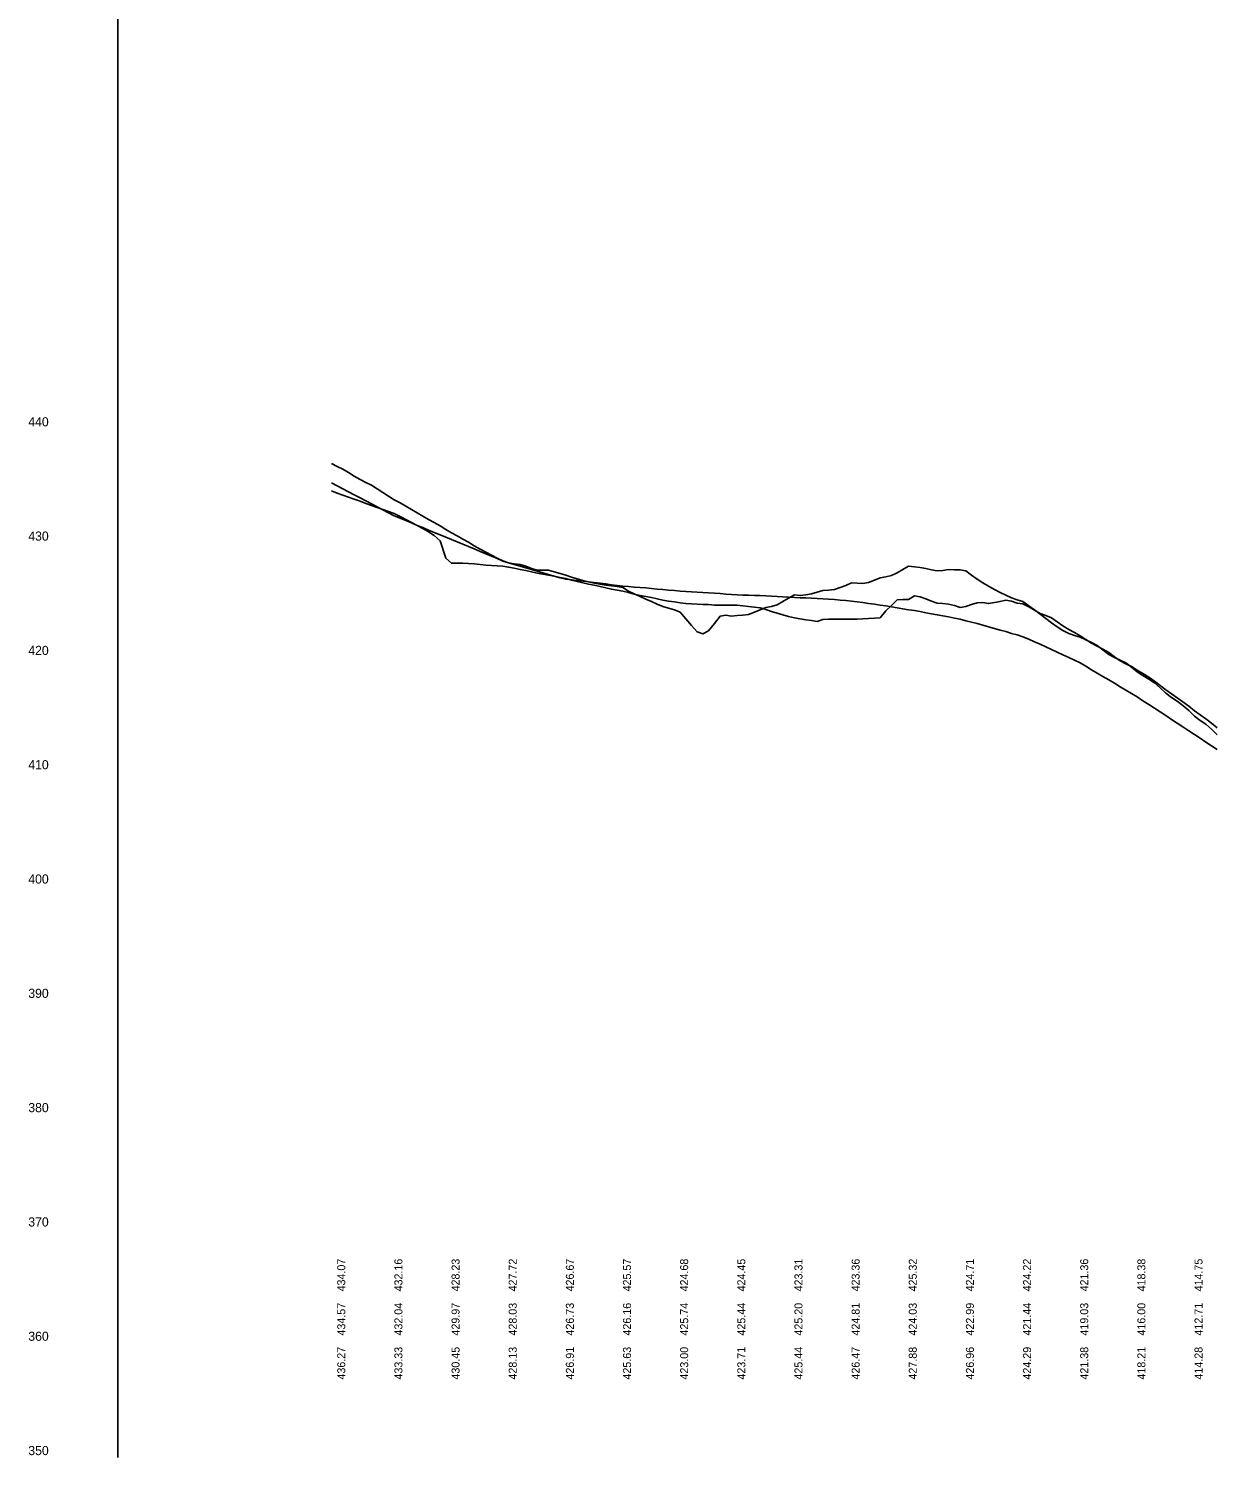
# Model space of a CAD drawing. Extents: x 2116146 to 2121546, y 979095 to 984095.
# Drawn here: x 2117491 to 2118529, y 981595 to 982845 of the extents above; entities that cross this region are included whole.
import ezdxf

# ---------------------------------------------------------------- set-up
doc = ezdxf.new("R2010")
doc.units = 0
for name, color, linetype in [('RD_DDB_ElevTX', 7, 'Continuous'), ('RD_DDB_Profile_EX', 7, 'Continuous'), ('RD_DDB_StripGrade', 7, 'Continuous'), ('RD_GPK_Profile_Cell', 7, 'Continuous'), ('RD_Sketch2', 7, 'Continuous')]:
    doc.layers.add(name, color=color, linetype=linetype)

msp = doc.modelspace()

# ---------------------------------------------------------------- linework, layer by layer
at = {"layer": 'RD_DDB_Profile_EX'}
for points in [[(2117756, 982448.1), (2117761, 982445.5), (2117766, 982442.8), (2117771, 982440.2), (2117776, 982437.6), (2117781, 982434.9), (2117786, 982432.3), (2117791, 982429.7), (2117796, 982427), (2117801, 982424.4), (2117806, 982421.7), (2117811, 982419.2), (2117816, 982417.2), (2117821, 982415.1), (2117826, 982413), (2117831, 982410.9), (2117836, 982408.9), (2117841, 982406.8), (2117846, 982404.7), (2117851, 982402.6), (2117856, 982400.6), (2117861, 982398.5), (2117866, 982396.4), (2117871, 982394.4), (2117876, 982392.3), (2117881, 982390.2), (2117886, 982388.1), (2117891, 982386.1), (2117896, 982384), (2117901, 982381.9), (2117906, 982379.7), (2117911, 982378), (2117916, 982376.6), (2117921, 982375.2), (2117926, 982373.8), (2117931, 982372.4), (2117936, 982370.9), (2117941, 982369.4), (2117946, 982367.9), (2117951, 982366.4), (2117956, 982364.9), (2117961, 982363.7), (2117966, 982363.1), (2117971, 982362.6), (2117976, 982362.1), (2117981, 982361.5), (2117986, 982360.9), (2117991, 982360.2), (2117996, 982359.6), (2118001, 982358.9), (2118006, 982358.2), (2118011, 982357.6), (2118016, 982357.3), (2118021, 982356.9), (2118026, 982356.5), (2118031, 982356.1), (2118036, 982355.7), (2118041, 982355.2), (2118046, 982354.8), (2118051, 982354.3), (2118056, 982353.8), (2118061, 982353.3), (2118066, 982353), (2118071, 982352.8), (2118076, 982352.5), (2118081, 982352.2), (2118086, 982351.8), (2118091, 982351.5), (2118096, 982351.2), (2118101, 982350.8), (2118106, 982350.4), (2118111, 982350.1), (2118116, 982349.9), (2118121, 982349.8), (2118126, 982349.6), (2118131, 982349.4), (2118136, 982349.2), (2118141, 982349), (2118146, 982348.7), (2118151, 982348.4), (2118156, 982348.2), (2118161, 982347.9), (2118166, 982347.6), (2118171, 982347.4), (2118176, 982347.1), (2118181, 982346.8), (2118186, 982346.5), (2118191, 982346.2), (2118196, 982345.9), (2118201, 982345.5), (2118206, 982345.1), (2118211, 982344.7), (2118216, 982344), (2118221, 982343.3), (2118226, 982342.6), (2118231, 982341.9), (2118236, 982341.1), (2118241, 982340.4), (2118246, 982339.6), (2118251, 982338.8), (2118256, 982338)], [(2118256, 982338), (2118261, 982337.1), (2118266, 982336.3), (2118271, 982335.4), (2118276, 982334.5), (2118281, 982333.6), (2118286, 982332.7), (2118291, 982331.7), (2118296, 982330.8), (2118301, 982329.8), (2118306, 982328.8), (2118311, 982327.5), (2118316, 982326.2), (2118321, 982324.9), (2118326, 982323.5), (2118331, 982322.1), (2118336, 982320.7), (2118341, 982319.3), (2118346, 982317.9), (2118351, 982316.4), (2118356, 982315), (2118361, 982313.5), (2118366, 982311.3), (2118371, 982309), (2118376, 982306.8), (2118381, 982304.5), (2118386, 982302.2), (2118391, 982299.9), (2118396, 982297.6), (2118401, 982295.3), (2118406, 982292.9), (2118411, 982290.6), (2118416, 982287.6), (2118421, 982284.6), (2118426, 982281.7), (2118431, 982278.7), (2118436, 982275.7), (2118441, 982272.7), (2118446, 982269.7), (2118451, 982266.7), (2118456, 982263.8), (2118461, 982260.8), (2118466, 982257.5), (2118471, 982254.2), (2118476, 982251), (2118481, 982247.7), (2118486, 982244.4), (2118491, 982241.1), (2118496, 982237.8), (2118501, 982234.5), (2118506, 982231.2), (2118511, 982227.9), (2118516, 982224.6), (2118521, 982221.3), (2118526, 982218.1), (2118531, 982214.8)]]:
    msp.add_lwpolyline(points, dxfattribs=at)
at = {"layer": 'RD_GPK_Profile_Cell'}
msp.add_line((2117569.1, 981595.5), (2117569.1, 984095.5), dxfattribs=at)
at = {"layer": 'RD_Sketch2'}
for points in [[(2117756, 982464.9), (2117761, 982462.5), (2117766, 982460), (2117771, 982457.1), (2117776, 982453.8), (2117781, 982450.9), (2117786, 982448.4), (2117791, 982445.9), (2117796, 982442.8), (2117801, 982439.5), (2117806, 982436.3), (2117811, 982433.3), (2117816, 982430.5), (2117821, 982427.7), (2117826, 982424.8), (2117831, 982421.8), (2117836, 982418.8), (2117841, 982416), (2117846, 982413.3), (2117851, 982410.4), (2117856, 982407.4), (2117861, 982404.4), (2117866, 982401.7), (2117871, 982398.9), (2117876, 982396.1), (2117881, 982393.1), (2117886, 982390.1), (2117891, 982387.4), (2117896, 982384.8), (2117901, 982382.3), (2117906, 982379.8), (2117911, 982378), (2117916, 982377.2), (2117921, 982376.5), (2117926, 982375.2), (2117931, 982373.2), (2117936, 982371.7), (2117941, 982371.6), (2117946, 982371.7), (2117951, 982370.3), (2117956, 982368.9), (2117961, 982367.3), (2117966, 982365.6), (2117971, 982364), (2117976, 982362.7), (2117981, 982361.4), (2117986, 982360.3), (2117991, 982359.3), (2117996, 982358.5), (2118001, 982357.9), (2118006, 982357.3), (2118011, 982356.4), (2118016, 982353.4), (2118021, 982350.9), (2118026, 982348.5), (2118031, 982346.4), (2118036, 982344.3), (2118041, 982341.9), (2118046, 982339.8), (2118051, 982338.3), (2118056, 982336.9), (2118061, 982335), (2118066, 982329.1), (2118071, 982323.3), (2118076, 982317.7), (2118081, 982315.9), (2118086, 982318.7), (2118091, 982324.9), (2118096, 982331.4), (2118101, 982332.2), (2118106, 982331.5), (2118111, 982331.9), (2118116, 982332.3), (2118121, 982332.8), (2118126, 982334.8), (2118131, 982336.9), (2118136, 982338.9), (2118141, 982339.9), (2118146, 982341.5), (2118151, 982344.3), (2118156, 982347.3), (2118161, 982350.1), (2118166, 982349.6), (2118171, 982350), (2118176, 982351.1), (2118181, 982352.4), (2118186, 982353.8), (2118191, 982354.2), (2118196, 982354.8), (2118201, 982356.4), (2118206, 982358.4), (2118211, 982360.5), (2118216, 982360.2), (2118221, 982360.1), (2118226, 982360.9), (2118231, 982362.8), (2118236, 982364.9), (2118241, 982365.8), (2118246, 982366.9), (2118251, 982369.3), (2118256, 982372.3)], [(2117756, 982441), (2117761, 982439.1), (2117766, 982437.3), (2117771, 982435.5), (2117776, 982433.7), (2117781, 982431.9), (2117786, 982430), (2117791, 982428.2), (2117796, 982426.5), (2117801, 982424.7), (2117806, 982422.9), (2117811, 982421.3), (2117816, 982418.7), (2117821, 982416.1), (2117826, 982413.5), (2117831, 982410.9), (2117836, 982408.1), (2117841, 982405.1), (2117846, 982402.1), (2117851, 982397.2), (2117856, 982382.1), (2117861, 982377.7), (2117866, 982377.7), (2117871, 982377.8), (2117876, 982377.6), (2117881, 982377.1), (2117886, 982376.6), (2117891, 982376.2), (2117896, 982375.7), (2117901, 982375.5), (2117906, 982375.1), (2117911, 982374.4), (2117916, 982373.3), (2117921, 982372.3), (2117926, 982371.3), (2117931, 982370.3), (2117936, 982369.2), (2117941, 982368.2), (2117946, 982367.2), (2117951, 982366.3), (2117956, 982365.3), (2117961, 982364.3), (2117966, 982363), (2117971, 982361.7), (2117976, 982360.5), (2117981, 982359.3), (2117986, 982358.5), (2117991, 982357.3), (2117996, 982356.2), (2118001, 982355), (2118006, 982354.3), (2118011, 982353.3), (2118016, 982352), (2118021, 982350.7), (2118026, 982349.4), (2118031, 982348.7), (2118036, 982347.7), (2118041, 982346.6), (2118046, 982345.5), (2118051, 982344.5), (2118056, 982344), (2118061, 982343.2), (2118066, 982342.6), (2118071, 982342.1), (2118076, 982341.9), (2118081, 982341.7), (2118086, 982341.6), (2118091, 982341.2), (2118096, 982341.1), (2118101, 982341.1), (2118106, 982341.1), (2118111, 982341.1), (2118116, 982340.4), (2118121, 982339.8), (2118126, 982339.2), (2118131, 982338.6), (2118136, 982337.3), (2118141, 982335.6), (2118146, 982334), (2118151, 982332.6), (2118156, 982331.2), (2118161, 982330), (2118166, 982329.1), (2118171, 982328.3), (2118176, 982327.6), (2118181, 982326.9), (2118186, 982328.4), (2118191, 982328.9), (2118196, 982328.8), (2118201, 982328.7), (2118206, 982328.8), (2118211, 982328.9), (2118216, 982328.9), (2118221, 982329.1), (2118226, 982329.3), (2118231, 982329.7), (2118236, 982330.1), (2118241, 982336.2), (2118246, 982340.9), (2118251, 982345.7), (2118256, 982346.1)], [(2118256, 982372.3), (2118261, 982375.1), (2118266, 982374.5), (2118271, 982374.1), (2118276, 982373), (2118281, 982371.9), (2118286, 982371), (2118291, 982371.5), (2118296, 982372.3), (2118301, 982372), (2118306, 982372), (2118311, 982371.1), (2118316, 982367.3), (2118321, 982363.7), (2118326, 982360.5), (2118331, 982357.6), (2118336, 982354.9), (2118341, 982352.2), (2118346, 982349.7), (2118351, 982347.6), (2118356, 982345.8), (2118361, 982344.2), (2118366, 982340.5), (2118371, 982337), (2118376, 982333.3), (2118381, 982329.4), (2118386, 982325.7), (2118391, 982322.2), (2118396, 982319), (2118401, 982316.3), (2118406, 982314.6), (2118411, 982313.1), (2118416, 982310.8), (2118421, 982308.3), (2118426, 982305.9), (2118431, 982301.9), (2118436, 982297.9), (2118441, 982295.2), (2118446, 982293), (2118451, 982290.7), (2118456, 982286.7), (2118461, 982282.7), (2118466, 982279.6), (2118471, 982276.4), (2118476, 982273.1), (2118481, 982268.7), (2118486, 982264.2), (2118491, 982260.4), (2118496, 982257.2), (2118501, 982253.4), (2118506, 982248.8), (2118511, 982244.1), (2118516, 982240.3), (2118521, 982237.1), (2118526, 982232.6), (2118531, 982227.7)], [(2118256, 982346.1), (2118261, 982346.1), (2118266, 982349.1), (2118271, 982348.4), (2118276, 982346.6), (2118281, 982344.6), (2118286, 982342.8), (2118291, 982342.4), (2118296, 982341.8), (2118301, 982340.7), (2118306, 982338.9), (2118311, 982339.9), (2118316, 982341.6), (2118321, 982343.2), (2118326, 982343.3), (2118331, 982342.4), (2118336, 982343.3), (2118341, 982344.4), (2118346, 982345.3), (2118351, 982344.6), (2118356, 982342.7), (2118361, 982342.2), (2118366, 982339.5), (2118371, 982336.6), (2118376, 982333.7), (2118381, 982332.1), (2118386, 982330.1), (2118391, 982326.6), (2118396, 982322.9), (2118401, 982319.8), (2118406, 982317.2), (2118411, 982314.3), (2118416, 982311.1), (2118421, 982307.8), (2118426, 982305.1), (2118431, 982302.5), (2118436, 982299.6), (2118441, 982296), (2118446, 982292.4), (2118451, 982289.8), (2118456, 982287.3), (2118461, 982284.3), (2118466, 982281.4), (2118471, 982278), (2118476, 982274.6), (2118481, 982270.8), (2118486, 982267), (2118491, 982263.4), (2118496, 982260), (2118501, 982256.4), (2118506, 982252.6), (2118511, 982248.7), (2118516, 982245.1), (2118521, 982241.6), (2118526, 982237.7), (2118531, 982233.7)]]:
    msp.add_lwpolyline(points, dxfattribs=at)

# ---------------------------------------------------------------- texts
at = {"layer": 'RD_DDB_ElevTX'}
for s, p in [('440', (2117490.8, 982497.5)), ('430', (2117490.8, 982397.5)), ('420', (2117490.8, 982297.5)), ('410', (2117490.8, 982197.5)), ('400', (2117490.8, 982097.5)), ('390', (2117490.8, 981997.5)), ('380', (2117490.8, 981897.5)), ('370', (2117490.8, 981797.5)), ('360', (2117490.8, 981697.5)), ('350', (2117490.8, 981597.5))]:
    msp.add_text(s, height=8, dxfattribs=at).set_placement(p)
at = {"layer": 'RD_DDB_StripGrade'}
for s, p in [('434.57', (2117768.1, 981702.1)), ('432.04', (2117818.1, 981702.1)), ('429.97', (2117868.1, 981702.1)), ('428.03', (2117918.1, 981702.1)), ('426.73', (2117968.1, 981702.1)), ('426.16', (2118018.1, 981702.1)), ('425.74', (2118068.1, 981702.1)), ('425.44', (2118118.1, 981702.1)), ('425.20', (2118168.1, 981702.1)), ('424.81', (2118218.1, 981702.1)), ('424.03', (2118268.1, 981702.1)), ('422.99', (2118318.1, 981702.1)), ('421.44', (2118368.1, 981702.1)), ('419.03', (2118418.1, 981702.1)), ('416.00', (2118468.1, 981702.1)), ('412.71', (2118518.1, 981702.1))]:
    msp.add_text(s, height=7, rotation=90, dxfattribs=at).set_placement(p)
at = {"layer": 'RD_GPK_Profile_Cell'}
for s in ['154', 'S765', '2200.000000', '350', '100', '10', 'NOGAP']:
    msp.add_text(s, height=0.00975, dxfattribs=at).set_placement((2117569.1, 981595.5))
at = {"layer": 'RD_Sketch2'}
for s, p in [('434.07', (2117768.1, 981740.7)), ('432.16', (2117818.1, 981740.7)), ('428.23', (2117868.1, 981740.7)), ('427.72', (2117918.1, 981740.7)), ('426.67', (2117968.1, 981740.7)), ('425.57', (2118018.1, 981740.7)), ('424.68', (2118068.1, 981740.7)), ('424.45', (2118118.1, 981740.7)), ('423.31', (2118168.1, 981740.7)), ('423.36', (2118218.1, 981740.7)), ('425.32', (2118268.1, 981740.7)), ('424.71', (2118318.1, 981740.7)), ('424.22', (2118368.1, 981740.7)), ('421.36', (2118418.1, 981740.7)), ('418.38', (2118468.1, 981740.7)), ('414.75', (2118518.1, 981740.7)), ('436.27', (2117768.1, 981663.6)), ('433.33', (2117818.1, 981663.6)), ('430.45', (2117868.1, 981663.6)), ('428.13', (2117918.1, 981663.6)), ('426.91', (2117968.1, 981663.6)), ('425.63', (2118018.1, 981663.6)), ('423.00', (2118068.1, 981663.6)), ('423.71', (2118118.1, 981663.6)), ('425.44', (2118168.1, 981663.6)), ('426.47', (2118218.1, 981663.6)), ('427.88', (2118268.1, 981663.6)), ('426.96', (2118318.1, 981663.6)), ('424.29', (2118368.1, 981663.6)), ('421.38', (2118418.1, 981663.6)), ('418.21', (2118468.1, 981663.6)), ('414.28', (2118518.1, 981663.6))]:
    msp.add_text(s, height=7, rotation=90, dxfattribs=at).set_placement(p)

doc.saveas('drawing.dxf')
